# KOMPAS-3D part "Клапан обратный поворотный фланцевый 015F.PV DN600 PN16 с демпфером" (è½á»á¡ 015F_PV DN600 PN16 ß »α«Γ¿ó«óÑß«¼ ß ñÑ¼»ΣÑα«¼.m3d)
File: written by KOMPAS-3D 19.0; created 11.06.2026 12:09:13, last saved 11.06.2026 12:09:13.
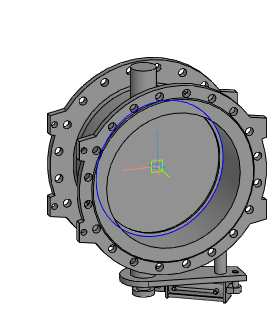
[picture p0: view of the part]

Document properties: Автор: Энергия; Полное имя файла: Z:\3.Личные\kachalov\001_3d для проектировщиков\5.5 Тип 015F.PV Клапан обратный поворотный с двумя эксцентриками\_stp_Клапан 015F.PV DN300-DN1200 с противовесом с демпфером\Клапан 015F_PV DN600 PN16 с противовесом с демпфером.m3d

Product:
- Part/product: Клапан обратный поворотный фланцевый 015F.PV DN600 PN16 с демпфером

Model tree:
1. Операция без истории:1
2. Сплайн:1
     Координата Y = 30; Координата Z = 300; Вес = 1; Координата X = 600; Координата Y = 108.991; Координата Z = 300; Вес = 0.333333; Координата X = 600; Координата Y = 108.991; Координата Z = -300; Вес = 0.333333; Координата Y = 30; Координата Z = -300; Вес = 1; Координата X = -600; Координата Y = -48.9915; Координата Z = -300; Вес = 0.333333; Координата X = -600; Координата Y = -48.9915; Координата Z = 300; Вес = 0.333333; Порядок = 4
